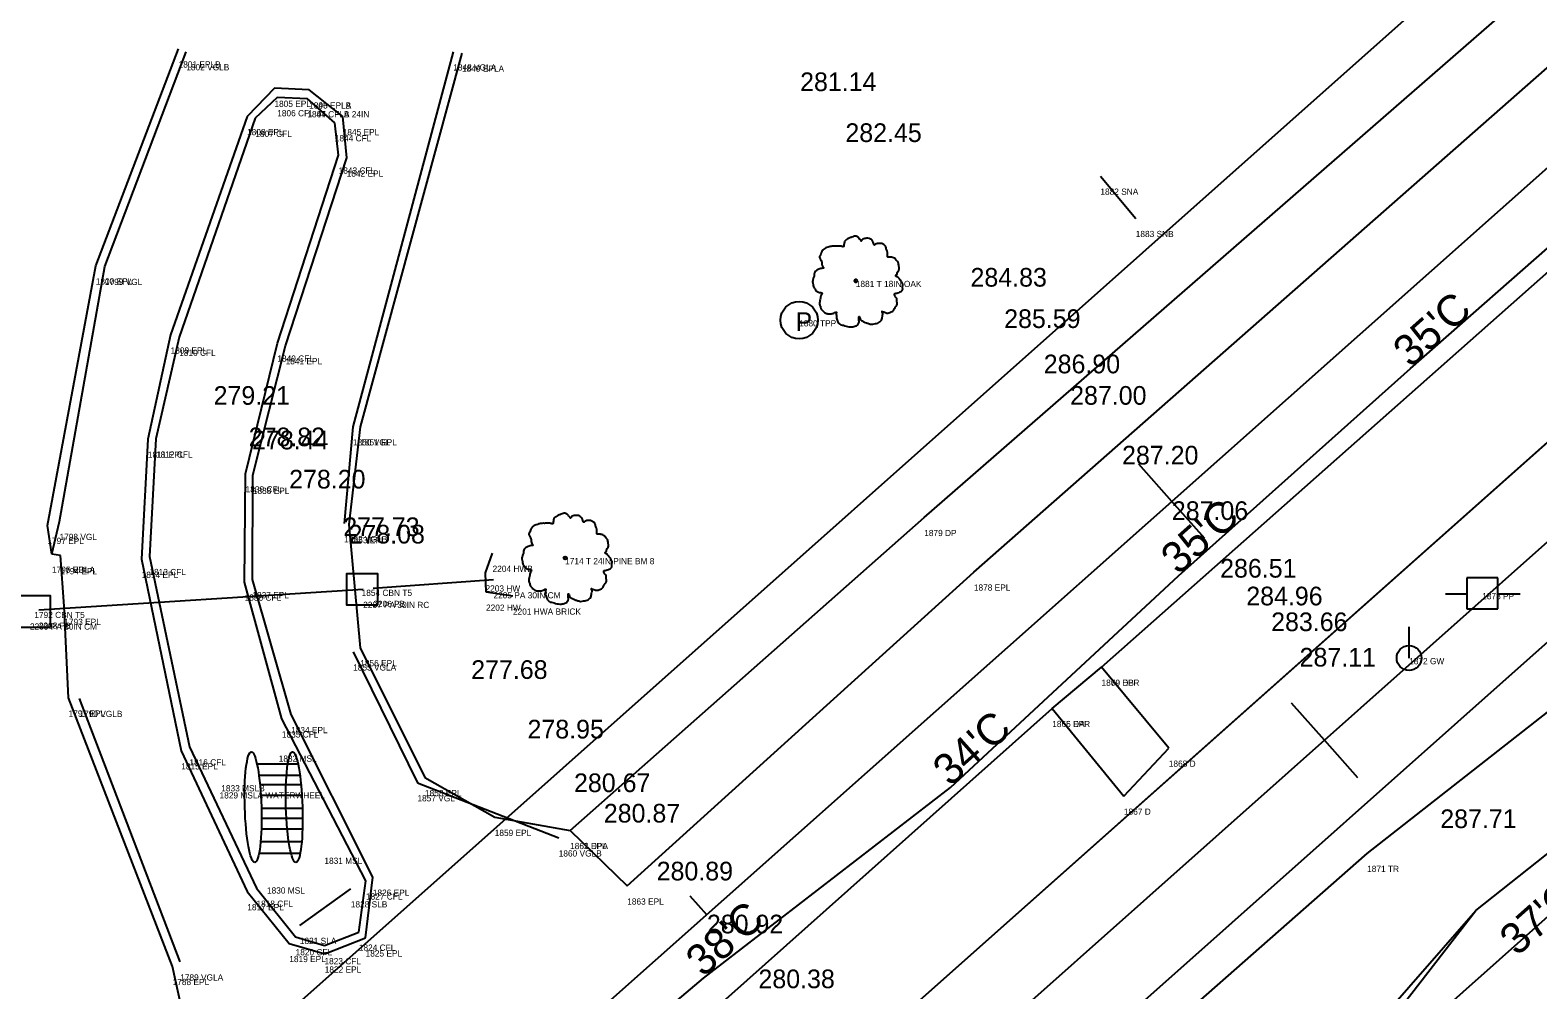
# Model space of a CAD drawing. Extents: x 49683 to 58852, y 49525 to 54803.
# Drawn here: x 55724.8 to 55967.1, y 53594.5 to 53748.8 of the extents above; entities that cross this region are included whole.
import ezdxf

# ---------------------------------------------------------------- set-up
doc = ezdxf.new("R2010")
doc.units = 0
for name, color, linetype in [('Level 1', 7, 'Continuous'), ('Level 11', 7, 'Continuous'), ('Level 13', 7, 'Continuous'), ('Level 18', 7, 'Continuous'), ('Level 19', 7, 'Continuous'), ('Level 2', 7, 'Continuous'), ('Level 20', 7, 'Continuous'), ('Level 3', 7, 'Continuous'), ('Level 32', 7, 'Continuous'), ('Level 33', 7, 'Continuous'), ('Level 48', 7, 'Continuous'), ('Level 5', 7, 'Continuous'), ('Level 52', 7, 'Continuous'), ('Level 53', 7, 'Continuous'), ('Level 55', 7, 'Continuous'), ('Level 56', 7, 'Continuous'), ('Level 58', 7, 'Continuous'), ('Level 59', 7, 'Continuous'), ('Level 6', 7, 'Continuous'), ('Level 61', 7, 'Continuous'), ('Level 8', 7, 'Continuous'), ('Level 9', 7, 'Continuous')]:
    doc.layers.add(name, color=color, linetype=linetype)

# ---------------------------------------------------------------- blocks, each defined once
blk = doc.blocks.new('T1')
at = {"layer": 'Level 11'}
for centre, radius in [((0, 0), 0.25), ((-0.01, -0.02), 0.0001)]:
    blk.add_circle(centre, radius, dxfattribs=at)
for points in [[(0.13, 7.17), (-0.17, 7.19), (-0.49, 7.09), (-0.74, 6.99), (-0.97, 6.92), (-1.19, 6.82), (-1.49, 6.64), (-1.72, 6.44), (-1.84, 6.19), (-1.89, 5.97), (-1.94, 5.69), (-1.94, 5.52), (-2.07, 5.49), (-2.22, 5.52), (-2.47, 5.59), (-2.72, 5.59), (-2.97, 5.59), (-3.32, 5.57), (-3.67, 5.57), (-3.94, 5.52), (-4.27, 5.47), (-4.64, 5.34), (-4.99, 5.22), (-5.29, 4.97), (-5.54, 4.49), (-5.67, 4.14), (-5.82, 3.89), (-5.67, 3.44), (-5.49, 3.09), (-5.47, 2.89), (-5.39, 2.47), (-5.29, 2.24), (-5.17, 2.04), (-5.24, 2.02), (-5.62, 1.97), (-5.92, 1.87), (-6.34, 1.64), (-6.57, 1.42), (-6.67, 1.09), (-6.69, 0.75), (-6.79, 0.55), (-6.87, 0.27), (-6.89, 0.2), (-6.94, -0.13), (-6.84, -0.58), (-6.82, -0.93), (-6.69, -1.15), (-6.54, -1.33), (-6.37, -1.58), (-5.97, -1.8), (-5.64, -1.9), (-5.44, -1.93), (-5.62, -2.43), (-5.67, -2.78), (-5.79, -3.18), (-5.79, -3.25), (-5.84, -3.73), (-5.69, -4.05), (-5.62, -4.43), (-5.44, -4.65), (-5.17, -4.95), (-4.84, -5.18), (-4.34, -5.3), (-3.94, -5.28), (-3.37, -5.1), (-3.12, -5.03), (-3.14, -5.2), (-3.12, -5.58), (-3.12, -6), (-2.97, -6.33), (-2.87, -6.6), (-2.72, -6.85), (-2.39, -7.08), (-1.99, -7.15), (-1.57, -7.3), (-1.12, -7.38), (-0.62, -7.4), (-0.02, -7.25), (0.26, -7.13), (0.36, -6.95), (0.56, -6.58), (0.51, -6.35), (0.53, -5.75), (0.63, -5.93), (0.81, -6.28), (1.31, -6.58), (1.71, -6.75), (2.18, -6.9), (2.48, -6.98), (2.96, -6.9), (3.33, -6.83), (3.71, -6.7), (4.01, -6.43), (4.18, -6.15), (4.23, -5.88), (4.31, -5.5), (4.36, -5.33)], [(4.36, -5.33), (4.28, -5.15), (4.23, -4.9), (4.31, -4.93), (4.48, -4.98), (4.75, -5.1), (4.98, -5.18), (5.3, -5.15), (5.58, -5.05), (6.03, -4.78), (6.3, -4.3), (6.58, -3.9), (6.65, -3.58), (6.6, -3.35), (6.58, -2.85), (6.38, -2.6), (6.33, -2.48), (6.23, -2.08), (6.3, -2.03), (6.58, -1.98), (6.95, -1.85), (7.23, -1.73), (7.45, -1.55), (7.53, -1.33), (7.5, -0.93), (7.55, -0.53), (7.48, -0.38), (7.38, -0.23), (7.3, -0.03), (7.15, 0.12), (7.05, 0.27), (6.95, 0.37), (6.83, 0.52), (6.65, 0.65), (6.5, 0.7), (6.45, 0.85), (6.6, 1.04), (6.65, 1.14), (6.68, 1.37), (6.9, 1.72), (6.95, 2.12), (6.9, 2.54), (6.85, 2.82), (6.7, 3.09), (6.5, 3.34), (6.38, 3.52), (6.2, 3.64), (5.88, 3.77), (5.63, 3.82), (5.28, 3.82), (5.08, 3.87), (5.1, 3.92), (5.1, 4.07), (5.1, 4.34), (5.03, 4.79), (4.88, 5.29), (4.88, 5.32), (4.78, 5.57), (4.56, 5.77), (4.38, 5.87), (4.18, 5.99), (3.93, 6.02), (3.63, 6.02), (3.36, 5.97), (3.16, 5.87), (2.98, 5.74), (2.91, 5.89), (2.81, 6.19), (2.76, 6.34), (2.61, 6.52), (2.38, 6.72), (1.93, 6.84), (1.31, 6.77), (1.01, 6.57), (0.86, 6.39), (0.81, 6.52), (0.61, 6.72), (0.51, 6.89), (0.33, 7.02), (0.18, 7.12), (0.08, 7.17)]]:
    blk.add_spline(points, degree=3, dxfattribs=at)
blk = doc.blocks.new('CB')
at = {"layer": 'Level 6'}
blk.add_line((2.59, -2.45), (2.59, 2.55), dxfattribs=at)
blk.add_lwpolyline([(2.59, -2.45), (2.59, 2.55), (-2.41, 2.55), (-2.41, -2.45)], close=True, dxfattribs=at)
blk = doc.blocks.new('GW')
at = {"layer": 'Level 9'}
blk.add_line((0, 0), (0, 5), dxfattribs=at)
blk.add_circle((0, 0), 2, dxfattribs=at)
blk = doc.blocks.new('PP')
at = {"layer": 'Level 9'}
for p, q in [((2.53, 2.45), (-2.47, 2.45)), ((-2.47, 2.45), (-2.47, -2.55)), ((2.53, -2.55), (2.53, 2.45)), ((-5.91, -0.11), (-2.44, -0.11)), ((2.45, -0.11), (6.09, -0.11)), ((-2.47, -2.55), (2.53, -2.55))]:
    blk.add_line(p, q, dxfattribs=at)
blk = doc.blocks.new('TPP')
at = {"layer": 'Level 9'}
blk.add_circle((0, 0), 3, dxfattribs=at)
blk.add_text('P', height=3, dxfattribs=at).set_placement((-0.59, -1.73))

msp = doc.modelspace()

# ---------------------------------------------------------------- linework, layer by layer
at = {"layer": 'Level 1'}
for p, q in [((55534.58, 53340.86), (56030.42, 53781.6)), ((55908.29, 53673.04), (55902.97, 53679.02)), ((55913.6, 53667.06), (55908.29, 53673.04)), ((55833.55, 53606.61), (55830.89, 53609.6))]:
    msp.add_line(p, q, dxfattribs=at)
at = {"layer": 'Level 11'}
for p, q in [((55939.67, 53616.48), (55996.99, 53661.35)), ((55725.8, 53428.27), (55939.67, 53616.48)), ((55768.17, 53604.91), (55776.36, 53610.79))]:
    msp.add_line(p, q, dxfattribs=at)
at = {"layer": 'Level 13'}
for p, q in [((55512.66, 53365.53), (56008.5, 53806.27)), ((55556.51, 53316.2), (56052.34, 53756.94))]:
    msp.add_line(p, q, dxfattribs=at)
at = {"layer": 'Level 18'}
for p, q in [((55946.66, 53694.37), (55984.18, 53727.42)), ((55909.35, 53661.08), (55946.66, 53694.37)), ((55872.7, 53627.06), (55909.35, 53661.08)), ((55957.14, 53607.32), (55996.36, 53638.46)), ((55833.01, 53596.44), (55872.7, 53627.06)), ((55923.96, 53569.38), (55957.14, 53607.32)), ((55926.22, 53567.41), (55957.14, 53607.32)), ((55794.83, 53564.14), (55833.01, 53596.44))]:
    msp.add_line(p, q, dxfattribs=at)
at = {"layer": 'Level 19'}
for p, q in [((54181.77, 52078.16), (56150.85, 53828.45)), ((55932.84, 53634.66), (55927.52, 53640.64)), ((55932.84, 53634.66), (55938.15, 53628.68))]:
    msp.add_line(p, q, dxfattribs=at)
at = {"layer": 'Level 2'}
for p, q in [((55761.27, 53630.88), (55767.88, 53630.88)), ((55761.59, 53629.03), (55768.2, 53629.03)), ((55761.76, 53627.54), (55768.37, 53627.54)), ((55761.9, 53625.83), (55768.51, 53625.83)), ((55762.04, 53623.76), (55768.66, 53623.76)), ((55761.99, 53620.42), (55768.6, 53620.42)), ((55762.02, 53622.13), (55768.63, 53622.13)), ((55761.87, 53618.36), (55768.48, 53618.36)), ((55761.63, 53616.51), (55768.24, 53616.51))]:
    msp.add_line(p, q, dxfattribs=at)
for centre in [(55760.66, 53623.91), (55767.27, 53623.91)]:
    msp.add_ellipse(centre, major_axis=(0.28, -8.89), ratio=0.149345, dxfattribs=at)
at = {"layer": 'Level 20'}
for p, q in [((55390.95, 53169.04), (56142.88, 53837.41)), ((55400.37, 53145.3), (56158.82, 53819.48))]:
    msp.add_line(p, q, dxfattribs=at)
at = {"layer": 'Level 3'}
for p, q in [((55735.38, 53710.89), (55748.69, 53745.76)), ((55876.48, 53661.69), (55974.42, 53747.84)), ((55736.84, 53710.81), (55749.93, 53745.3)), ((55792.82, 53745.28), (55776.71, 53685.03)), ((55794.23, 53745.08), (55777.88, 53685.03)), ((55764.09, 53739.43), (55759.69, 53734.89)), ((55769.67, 53739.17), (55764.09, 53739.43)), ((55775.06, 53734.88), (55769.67, 53739.17)), ((55764.54, 53737.92), (55761.02, 53734.6)), ((55769.38, 53737.75), (55764.54, 53737.92)), ((55773.79, 53733.89), (55769.38, 53737.75)), ((55759.69, 53734.89), (55747.41, 53699.79)), ((55761.02, 53734.6), (55748.79, 53699.42)), ((55774.41, 53728.7), (55773.79, 53733.89)), ((55775.7, 53728.22), (55775.06, 53734.88)), ((55764.56, 53698.49), (55774.41, 53728.7)), ((55765.89, 53698.06), (55775.7, 53728.22)), ((55896.99, 53646.4), (55989.61, 53728.42)), ((55727.61, 53669.19), (55735.38, 53710.89)), ((55729.56, 53669.83), (55736.84, 53710.81)), ((55747.41, 53699.79), (55743.75, 53683.05)), ((55748.79, 53699.42), (55745.06, 53683.07)), ((55759.47, 53677.48), (55764.56, 53698.49)), ((55760.63, 53677.24), (55765.89, 53698.06)), ((55743.75, 53683.05), (55742.75, 53663.74)), ((55745.06, 53683.07), (55744, 53664.19)), ((55776.71, 53685.03), (55775.3, 53669.47)), ((55777.88, 53685.03), (55776.07, 53669.32)), ((55759.3, 53660.08), (55759.47, 53677.48)), ((55760.55, 53660.47), (55760.63, 53677.24)), ((55728.35, 53664.56), (55727.61, 53669.19)), ((55728.35, 53664.56), (55729.56, 53669.83)), ((55776.07, 53669.32), (55777.88, 53649.53)), ((55729.72, 53664.33), (55728.35, 53664.56)), ((55730.33, 53656.18), (55729.72, 53664.33)), ((55742.75, 53663.74), (55749.12, 53632.96)), ((55744, 53664.19), (55750.43, 53633.6)), ((55820.78, 53611.24), (55876.48, 53661.69)), ((55765.29, 53638.09), (55759.3, 53660.08)), ((55766.77, 53638.79), (55760.55, 53660.47)), ((55731.02, 53641.45), (55730.33, 53656.18)), ((55776.74, 53648.86), (55787.07, 53627.83)), ((55777.88, 53649.53), (55788.28, 53628.66)), ((55889.07, 53639.77), (55896.99, 53646.4)), ((55747.73, 53598.31), (55731.02, 53641.45)), ((55748.95, 53599.04), (55732.76, 53641.39)), ((55836.6, 53593.06), (55889.07, 53639.77)), ((55778.8, 53612.05), (55765.29, 53638.09)), ((55779.9, 53612.66), (55766.77, 53638.79)), ((55749.12, 53632.96), (55759.73, 53610.33)), ((55750.43, 53633.6), (55761.2, 53610.89)), ((55787.07, 53627.83), (55809.77, 53618.97)), ((55788.28, 53628.66), (55799.49, 53622.27)), ((55799.49, 53622.27), (55811.6, 53620.16)), ((55811.6, 53620.16), (55820.78, 53611.24)), ((55778.74, 53602.9), (55779.9, 53612.66)), ((55759.73, 53610.33), (55766.48, 53602)), ((55761.2, 53610.89), (55767.5, 53603.09)), ((55777.65, 53603.83), (55778.8, 53612.05)), ((55767.5, 53603.09), (55772.13, 53601.65)), ((55772.13, 53601.65), (55777.65, 53603.83)), ((55772.17, 53600.31), (55778.74, 53602.9)), ((55766.48, 53602), (55772.17, 53600.31)), ((55754.48, 53567.23), (55747.73, 53598.31))]:
    msp.add_line(p, q, dxfattribs=at)
at = {"layer": 'Level 33'}
msp.add_line((55925.36, 53567.81), (56180.75, 53794.81), dxfattribs=at)
at = {"layer": 'Level 5'}
for p, q in [((55798.01, 53661.55), (55799.14, 53664.71)), ((55798.09, 53658.46), (55798.01, 53661.55)), ((55802.42, 53657.83), (55798.09, 53658.46))]:
    msp.add_line(p, q, dxfattribs=at)
at = {"layer": 'Level 6'}
for p, q in [((55778.35, 53658.9), (55726.23, 53655.57)), ((55799.29, 53660.45), (55779.97, 53659.06))]:
    msp.add_line(p, q, dxfattribs=at)
at = {"layer": 'Level 8'}
for p, q in [((55868.5, 53670.46), (55965.73, 53755.18)), ((55896.81, 53725.31), (55902.49, 53718.51)), ((55811.6, 53620.16), (55868.5, 53670.46)), ((55907.8, 53633.39), (55896.99, 53646.4)), ((55889.07, 53639.77), (55900.59, 53625.68)), ((55900.59, 53625.68), (55907.8, 53633.39))]:
    msp.add_line(p, q, dxfattribs=at)

# ---------------------------------------------------------------- block references
at = {"layer": 'Level 11'}
for p in [(55857.51, 53708.48), (55810.8, 53663.94)]:
    msp.add_blockref('T1', p, dxfattribs=at)
at = {"layer": 'Level 6'}
for p in [(55778.1, 53658.85), (55725.51, 53655.29)]:
    msp.add_blockref('CB', p, dxfattribs=at)
at = {"layer": 'Level 9'}
for name, p in [('TPP', (55848.41, 53702.16)), ('PP', (55958.16, 53658.32)), ('GW', (55946.42, 53647.87))]:
    msp.add_blockref(name, p, dxfattribs=at)

# ---------------------------------------------------------------- texts
at = {"layer": 'Level 32'}
for s, p in [('281.14', (55848.56, 53738.97)), ('282.45', (55855.84, 53730.79)), ('284.83', (55875.94, 53707.55)), ('285.59', (55881.35, 53700.9)), ('286.90', (55887.71, 53693.62)), ('279.21', (55754.32, 53688.56)), ('287.00', (55891.95, 53688.57)), ('278.82', (55759.96, 53681.9)), ('278.44', (55760.51, 53681.4)), ('287.20', (55900.29, 53678.97)), ('278.20', (55766.46, 53675.11)), ('287.06', (55908.29, 53670.05)), ('277.73', (55775.15, 53667.46)), ('278.08', (55776, 53666.27)), ('286.51', (55916.05, 53660.79)), ('284.96', (55920.25, 53656.33)), ('283.66', (55924.25, 53652.19)), ('287.11', (55928.82, 53646.5)), ('277.68', (55795.71, 53644.51)), ('278.95', (55804.76, 53634.94)), ('280.67', (55812.23, 53626.32)), ('280.87', (55817.02, 53621.43)), ('287.71', (55951.42, 53620.54)), ('280.89', (55825.51, 53612.13)), ('280.92', (55833.58, 53603.62)), ('280.38', (55841.87, 53594.81))]:
    msp.add_text(s, height=3, dxfattribs=at).set_placement(p)
at = {"layer": 'Level 48'}
for s, rotation, p in [("35'C", 41.6333, (55946.66, 53694.37)), ("35'C", 41.6334, (55909.35, 53661.08)), ("34'C", 41.6334, (55872.7, 53627.06)), ("37'C", 41.6334, (55963.78, 53599.84)), ("38'C", 41.6333, (55833.01, 53596.44))]:
    msp.add_text(s, height=5, rotation=rotation, dxfattribs=at).set_placement(p)
at = {"layer": 'Level 52'}
for s, p in [('1832 MSL ', (55764.78, 53631.2)), ('1833 MSLB ', (55755.55, 53626.44)), ('1829 MSLA WATERWHEEL ', (55755.27, 53625.3)), ('1831 MSL ', (55772.12, 53614.79)), ('1830 MSL ', (55762.89, 53610.02))]:
    msp.add_text(s, height=1, dxfattribs=at).set_placement(p)
at = {"layer": 'Level 53'}
for s, p in [('1801 EPLB ', (55748.69, 53742.76)), ('1802 VGLB ', (55749.93, 53742.3)), ('1848 VGLA ', (55792.82, 53742.28)), ('1849 EPLA ', (55794.23, 53742.08)), ('1805 EPL ', (55764.09, 53736.43)), ('1803 EPLA ', (55769.67, 53736.17)), ('1846 EPLB ', (55769.67, 53736.17)), ('1806 CFL ', (55764.54, 53734.92)), ('1804 CFLA 24IN ', (55769.38, 53734.75)), ('1847 CFLB ', (55769.38, 53734.75)), ('1808 EPL ', (55759.69, 53731.89)), ('1807 CFL ', (55761.02, 53731.6)), ('1844 CFL ', (55773.79, 53730.89)), ('1845 EPL ', (55775.06, 53731.88)), ('1843 CFL ', (55774.41, 53725.7)), ('1842 EPL ', (55775.7, 53725.22)), ('1800 EPL ', (55735.38, 53707.89)), ('1799 VGL ', (55736.84, 53707.81)), ('1809 EPL ', (55747.41, 53696.79)), ('1810 CFL ', (55748.79, 53696.42)), ('1840 CFL ', (55764.56, 53695.49)), ('1841 EPL ', (55765.89, 53695.06)), ('1850 VGL ', (55776.71, 53682.03)), ('1851 EPL ', (55777.88, 53682.03)), ('1811 EPL ', (55743.75, 53680.05)), ('1812 CFL ', (55745.06, 53680.07)), ('1839 CFL ', (55759.47, 53674.48)), ('1838 EPL ', (55760.63, 53674.24)), ('1797 EPL ', (55727.61, 53666.19)), ('1798 VGL ', (55729.56, 53666.83)), ('1852 VGLB ', (55775.3, 53666.47)), ('1853 EPL ', (55776.07, 53666.32)), ('1795 EPL ', (55728.35, 53661.56)), ('1796 VGLA ', (55728.35, 53661.56)), ('1794 EPL ', (55729.72, 53661.33)), ('1814 EPL ', (55742.75, 53660.74)), ('1813 CFL ', (55744, 53661.19)), ('1878 EPL ', (55876.48, 53658.69)), ('1836 CFL ', (55759.3, 53657.08)), ('1837 EPL ', (55760.55, 53657.47)), ('1793 EPL ', (55730.33, 53653.18)), ('1855 VGLA ', (55776.74, 53645.86)), ('1856 EPL ', (55777.88, 53646.53)), ('1870 EPR ', (55896.99, 53643.4)), ('1791 EPL ', (55731.02, 53638.45)), ('1790 VGLB ', (55732.76, 53638.39)), ('1834 EPL ', (55766.77, 53635.79)), ('1865 EPR ', (55889.07, 53636.77)), ('1835 CFL ', (55765.29, 53635.09)), ('1815 EPL ', (55749.12, 53629.96)), ('1816 CFL ', (55750.43, 53630.6)), ('1857 VGL ', (55787.07, 53624.83)), ('1858 EPL ', (55788.28, 53625.66)), ('1859 EPL ', (55799.49, 53619.27)), ('1861 EPL ', (55811.6, 53617.16)), ('1860 VGLB ', (55809.77, 53615.97)), ('1826 EPL ', (55779.9, 53609.66)), ('1817 EPL ', (55759.73, 53607.33)), ('1818 CFL ', (55761.2, 53607.89)), ('1827 CFL ', (55778.8, 53609.05)), ('1863 EPL ', (55820.78, 53608.24)), ('1820 CFL ', (55767.5, 53600.09)), ('1824 CFL ', (55777.65, 53600.83)), ('1825 EPL ', (55778.74, 53599.9)), ('1819 EPL ', (55766.48, 53599)), ('1823 CFL ', (55772.13, 53598.65)), ('1822 EPL ', (55772.17, 53597.31)), ('1788 EPL ', (55747.73, 53595.31)), ('1789 VGLA ', (55748.95, 53596.04))]:
    msp.add_text(s, height=1, dxfattribs=at).set_placement(p)
at = {"layer": 'Level 55'}
for s, p in [('2204 HWB ', (55799.14, 53661.71)), ('2203 HW ', (55798.01, 53658.55)), ('2202 HW ', (55798.09, 53655.46)), ('2201 HWA BRICK ', (55802.42, 53654.83))]:
    msp.add_text(s, height=1, dxfattribs=at).set_placement(p)
at = {"layer": 'Level 56'}
for s, p in [('1854 CBN T5 ', (55778.1, 53657.85)), ('2207 PA 30IN RC ', (55778.35, 53655.9)), ('2206 PB ', (55779.97, 53656.06)), ('2205 PA 30IN CM ', (55799.29, 53657.45)), ('1792 CBN T5 ', (55725.51, 53654.29)), ('2209 PA 30IN CM ', (55724.81, 53652.43)), ('2208 PB ', (55726.23, 53652.57))]:
    msp.add_text(s, height=1, dxfattribs=at).set_placement(p)
at = {"layer": 'Level 58'}
for s, p in [('1882 SNA ', (55896.81, 53722.31)), ('1883 SNB ', (55902.49, 53715.51)), ('1879 DP ', (55868.5, 53667.46)), ('1869 DB ', (55896.99, 53643.4)), ('1866 DA ', (55889.07, 53636.77)), ('1868 D ', (55907.8, 53630.39)), ('1867 D ', (55900.59, 53622.68)), ('1862 DPA ', (55811.6, 53617.16))]:
    msp.add_text(s, height=1, dxfattribs=at).set_placement(p)
at = {"layer": 'Level 59'}
for s, p in [('1880 TPP ', (55848.41, 53701.16)), ('1873 PP ', (55958.16, 53657.32)), ('1872 GW ', (55946.42, 53646.87))]:
    msp.add_text(s, height=1, dxfattribs=at).set_placement(p)
at = {"layer": 'Level 61'}
for s, p in [('1881 T 18IN OAK ', (55857.51, 53707.48)), ('1714 T 24IN PINE BM 8', (55810.8, 53662.94)), ('1871 TR ', (55939.67, 53613.48)), ('1828 SLB ', (55776.36, 53607.79)), ('1821 SLA ', (55768.17, 53601.91))]:
    msp.add_text(s, height=1, dxfattribs=at).set_placement(p)

doc.saveas('drawing.dxf')
